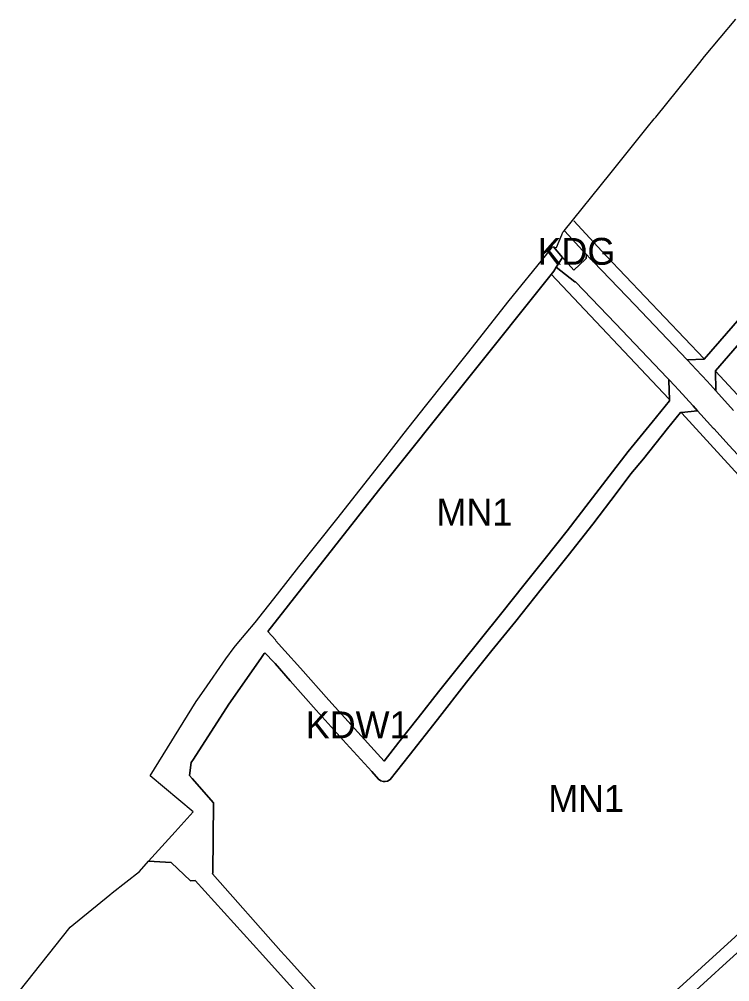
# Model space of a CAD drawing. Extents: x -284239 to -281592, y 34477 to 37267.
# Drawn here: x -283881 to -283616.2, y 35729.6 to 36088.2 of the extents above; entities that cross this region are included whole.
import ezdxf

# ---------------------------------------------------------------- set-up
doc = ezdxf.new("R2010")
doc.units = 0
for name, color, linetype in [('linie_rozgraniczajace', 7, 'Continuous'), ('linie_zabudowy_nieprzekraczalne', 7, 'Continuous'), ('oznaczenia_przeznaczen', 7, 'Continuous')]:
    doc.layers.add(name, color=color, linetype=linetype)

msp = doc.modelspace()

# ---------------------------------------------------------------- linework, layer by layer
at = {"layer": 'linie_rozgraniczajace'}
for points in [[(-283606.677, 35983.554), (-283625.75, 35961.486), (-283632.146, 35961.299), (-283651.553, 35981.775), (-283651.573, 35981.799), (-283666.956, 35997.773), (-283667.422, 35998.255), (-283667.642, 35998.485), (-283668.224, 35999.089), (-283669.613, 36000.531), (-283671.061, 36002.034), (-283677.733, 36009.181), (-283677.982, 36009.344), (-283660.95, 36030.4), (-283646.953, 36047.813), (-283644.36, 36051.04), (-283643.814, 36051.719), (-283627.43, 36072.1), (-283625.65, 36074.31), (-283613.963, 36088.161)], [(-283832.86, 35774.502), (-283822.95, 35785.5), (-283816.26, 35792.93), (-283832.3, 35806.38), (-283815.058, 35833.988), (-283814.47, 35834.93), (-283812.148, 35838.239), (-283803.99, 35849.862), (-283800.96, 35854.18), (-283799.793, 35855.563), (-283793.13, 35863.46), (-283784.81, 35874.03), (-283776.8, 35884.21), (-283762.68, 35901.95), (-283745.33, 35924.05), (-283737.56, 35934), (-283729.64, 35944), (-283714.02, 35963.62), (-283698.45, 35983.36), (-283684.92, 36000), (-283682.63, 36002.83), (-283682.24, 36003.4), (-283681.928, 36003.333), (-283678.505, 35999.421), (-283680.865, 35995.773), (-283681.793, 35994.34), (-283747.164, 35912.625), (-283788.411, 35860.094), (-283788.437, 35860.06), (-283785.455, 35856.88), (-283785.53, 35856.783), (-283782.047, 35852.838), (-283782.007, 35852.839), (-283776.177, 35846.403), (-283765.654, 35834.458), (-283757.35, 35825.329), (-283745.007, 35811.763), (-283739.547, 35818.873), (-283732.323, 35827.946), (-283724.815, 35837.644), (-283716.851, 35847.569), (-283709.286, 35857.04), (-283701.153, 35867.079), (-283693.019, 35877.346), (-283685.056, 35887.328), (-283676.808, 35897.652), (-283668.674, 35908.317), (-283661.223, 35918.015), (-283654.113, 35927.087), (-283645.126, 35938.036), (-283638.73, 35946.02), (-283638.73, 35946.418), (-283638.954, 35953.591), (-283638.927, 35953.917), (-283636.715, 35951.582), (-283635.367, 35950.159), (-283633.778, 35948.483), (-283631.306, 35945.744), (-283629.838, 35944.119), (-283628.194, 35942.297), (-283634.247, 35941.711), (-283634.604, 35941.632), (-283639.381, 35935.676), (-283648.425, 35924.414), (-283653.032, 35918.811), (-283658.208, 35912.042), (-283667.309, 35900.126), (-283676.467, 35888.437), (-283686.478, 35875.896), (-283695.977, 35863.979), (-283704.85, 35852.973), (-283714.292, 35841.17), (-283725.213, 35827.377), (-283735.735, 35813.925), (-283742.789, 35804.909), (-283743.812, 35804.341), (-283744.609, 35804.17), (-283745.405, 35804.17), (-283746.258, 35804.511), (-283747.112, 35805.137), (-283749.614, 35807.981), (-283759.17, 35818.418), (-283770.375, 35830.847), (-283780.102, 35841.682), (-283785.682, 35848.2), (-283785.718, 35848.198), (-283785.761, 35848.332), (-283786.219, 35848.802), (-283789.232, 35851.896), (-283789.496, 35852.162), (-283789.698, 35851.881), (-283790.953, 35850.09), (-283802.878, 35833.08), (-283816.126, 35812.589), (-283816.96, 35811.3), (-283817.54, 35806.42), (-283816.619, 35805.365), (-283808.67, 35796.25), (-283808.95, 35770.17), (-283808.955, 35769.886)], [(-283591.861, 35902.831), (-283616.44, 35929.426), (-283622.215, 35935.674), (-283622.244, 35935.71), (-283626.972, 35940.944), (-283628.194, 35942.297), (-283629.838, 35944.119), (-283631.306, 35945.744), (-283633.778, 35948.483), (-283635.367, 35950.159), (-283636.715, 35951.582), (-283638.927, 35953.917), (-283639.516, 35954.539), (-283658.789, 35974.876), (-283673.669, 35990.326), (-283673.962, 35990.308), (-283680.865, 35995.773), (-283678.505, 35999.421), (-283674.399, 35994.729), (-283669.942, 35998.815), (-283669.73, 35999.01), (-283669.613, 36000.531)], [(-283669.613, 36000.531), (-283668.224, 35999.089), (-283667.642, 35998.485), (-283667.422, 35998.255), (-283666.956, 35997.773), (-283651.573, 35981.799), (-283651.553, 35981.775), (-283632.146, 35961.299), (-283630.277, 35959.326), (-283628.885, 35957.858), (-283626.478, 35955.318), (-283626.441, 35955.261), (-283626.396, 35955.229), (-283624.783, 35953.442), (-283623.435, 35951.95), (-283621.467, 35949.769), (-283614.852, 35942.44)], [(-283602.166, 35979.602), (-283621.534, 35957.2), (-283621.467, 35949.769), (-283623.435, 35951.95), (-283624.783, 35953.442), (-283626.396, 35955.229), (-283626.441, 35955.261), (-283626.478, 35955.318), (-283628.885, 35957.858), (-283630.277, 35959.326), (-283632.146, 35961.299), (-283625.75, 35961.486), (-283606.677, 35983.554)], [(-283614.852, 35942.44), (-283621.467, 35949.769), (-283621.534, 35957.2), (-283602.166, 35979.602)], [(-283740.666, 35693.613), (-283780.8, 35738.036), (-283783.5, 35741.024), (-283808.955, 35769.886), (-283808.95, 35770.17), (-283808.67, 35796.25), (-283816.619, 35805.365), (-283817.54, 35806.42), (-283816.96, 35811.3), (-283816.126, 35812.589), (-283802.878, 35833.08), (-283790.953, 35850.09), (-283789.698, 35851.881), (-283789.496, 35852.162), (-283789.232, 35851.896), (-283786.219, 35848.802), (-283785.761, 35848.332), (-283785.718, 35848.198), (-283785.682, 35848.2), (-283780.102, 35841.682), (-283770.375, 35830.847), (-283759.17, 35818.418), (-283749.614, 35807.981), (-283747.112, 35805.137), (-283746.258, 35804.511), (-283745.405, 35804.17), (-283744.609, 35804.17), (-283743.812, 35804.341), (-283742.789, 35804.909), (-283735.735, 35813.925), (-283725.213, 35827.377), (-283714.292, 35841.17), (-283704.85, 35852.973), (-283695.977, 35863.979), (-283686.478, 35875.896), (-283676.467, 35888.437), (-283667.309, 35900.126), (-283658.208, 35912.042), (-283653.032, 35918.811), (-283648.425, 35924.414), (-283639.381, 35935.676), (-283634.604, 35941.632), (-283634.247, 35941.711), (-283628.194, 35942.297), (-283626.972, 35940.944), (-283622.244, 35935.71), (-283622.215, 35935.674), (-283616.44, 35929.426), (-283591.861, 35902.831)], [(-283881.05, 35726.03), (-283862.1, 35750), (-283847.259, 35761.98), (-283846.38, 35762.69), (-283836.24, 35770.75), (-283832.86, 35774.502), (-283824.445, 35774.068), (-283817.23, 35767.269), (-283817.232, 35767.227), (-283815.534, 35767.383), (-283790.273, 35739.559), (-283784.744, 35733.443), (-283735.174, 35678.603)], [(-283808.955, 35769.886), (-283783.5, 35741.024), (-283780.8, 35738.036), (-283740.666, 35693.613), (-283707.899, 35657.552), (-283705.683, 35657.06), (-283711.093, 35651.189), (-283711.377, 35652.06), (-283735.174, 35678.603), (-283784.744, 35733.443), (-283790.273, 35739.559), (-283815.534, 35767.383), (-283817.232, 35767.227), (-283817.23, 35767.269), (-283824.445, 35774.068), (-283832.86, 35774.502)], [(-283645.495, 35711.281), (-283623.204, 35731.542), (-283618.835, 35735.513), (-283588.953, 35762.48)], [(-283588.953, 35762.48), (-283618.835, 35735.513), (-283623.204, 35731.542), (-283645.495, 35711.281)]]:
    msp.add_lwpolyline(points, dxfattribs=at)
for points in [[(-283681.928, 36003.333), (-283680.74, 36003.08), (-283678.799, 36007.818), (-283678.79, 36007.84), (-283678.39, 36008.84), (-283677.982, 36009.344), (-283677.733, 36009.181), (-283671.061, 36002.034), (-283669.613, 36000.531), (-283669.73, 35999.01), (-283669.942, 35998.815), (-283674.399, 35994.729), (-283678.505, 35999.421)], [(-283788.437, 35860.06), (-283788.411, 35860.094), (-283747.164, 35912.625), (-283681.793, 35994.34), (-283680.865, 35995.773), (-283673.962, 35990.308), (-283673.669, 35990.326), (-283658.789, 35974.876), (-283639.516, 35954.539), (-283638.927, 35953.917), (-283638.954, 35953.591), (-283638.73, 35946.418), (-283638.73, 35946.02), (-283645.126, 35938.036), (-283654.113, 35927.087), (-283661.223, 35918.015), (-283668.674, 35908.317), (-283676.808, 35897.652), (-283685.056, 35887.328), (-283693.019, 35877.346), (-283701.153, 35867.079), (-283709.286, 35857.04), (-283716.851, 35847.569), (-283724.815, 35837.644), (-283732.323, 35827.946), (-283739.547, 35818.873), (-283745.007, 35811.763), (-283757.35, 35825.329), (-283765.654, 35834.458), (-283776.177, 35846.403), (-283782.007, 35852.839), (-283782.047, 35852.838), (-283785.53, 35856.783), (-283785.455, 35856.88)]]:
    msp.add_lwpolyline(points, close=True, dxfattribs=at)
at = {"layer": 'linie_zabudowy_nieprzekraczalne'}
for points in [[(-283674.342, 36013.038), (-283662.431, 36000.183), (-283625.795, 35961.722)], [(-283638.892, 35946.773), (-283682.738, 35993.159)], [(-283621.43, 35956.96), (-283583.055, 35915.583), (-283551.173, 35879.136), (-283500.779, 35822.096)], [(-283529.742, 35822.383), (-283529.742, 35824.5), (-283556.068, 35854.464), (-283597.078, 35900.964), (-283634.13, 35941.482)], [(-283703.254, 35666.597), (-283669.574, 35696.441), (-283633.723, 35728.654), (-283600.253, 35759.015), (-283562.286, 35793.411), (-283529.742, 35822.383)]]:
    msp.add_lwpolyline(points, dxfattribs=at)

# ---------------------------------------------------------------- texts
at = {"layer": 'oznaczenia_przeznaczen'}
for s, p in [('KDG', (-283687.846, 35996.714)), ('MN1', (-283725.52, 35899.569)), ('KDW1', (-283774.235, 35820.329)), ('MN1', (-283683.876, 35792.877))]:
    msp.add_text(s, height=10, dxfattribs=at).set_placement(p)

doc.saveas('drawing.dxf')
